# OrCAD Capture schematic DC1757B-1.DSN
size Custom; title: HIGH EFFICIENCY 12V / 12A BUCK-BOOST CONVERTER; rev: 1; company: TM
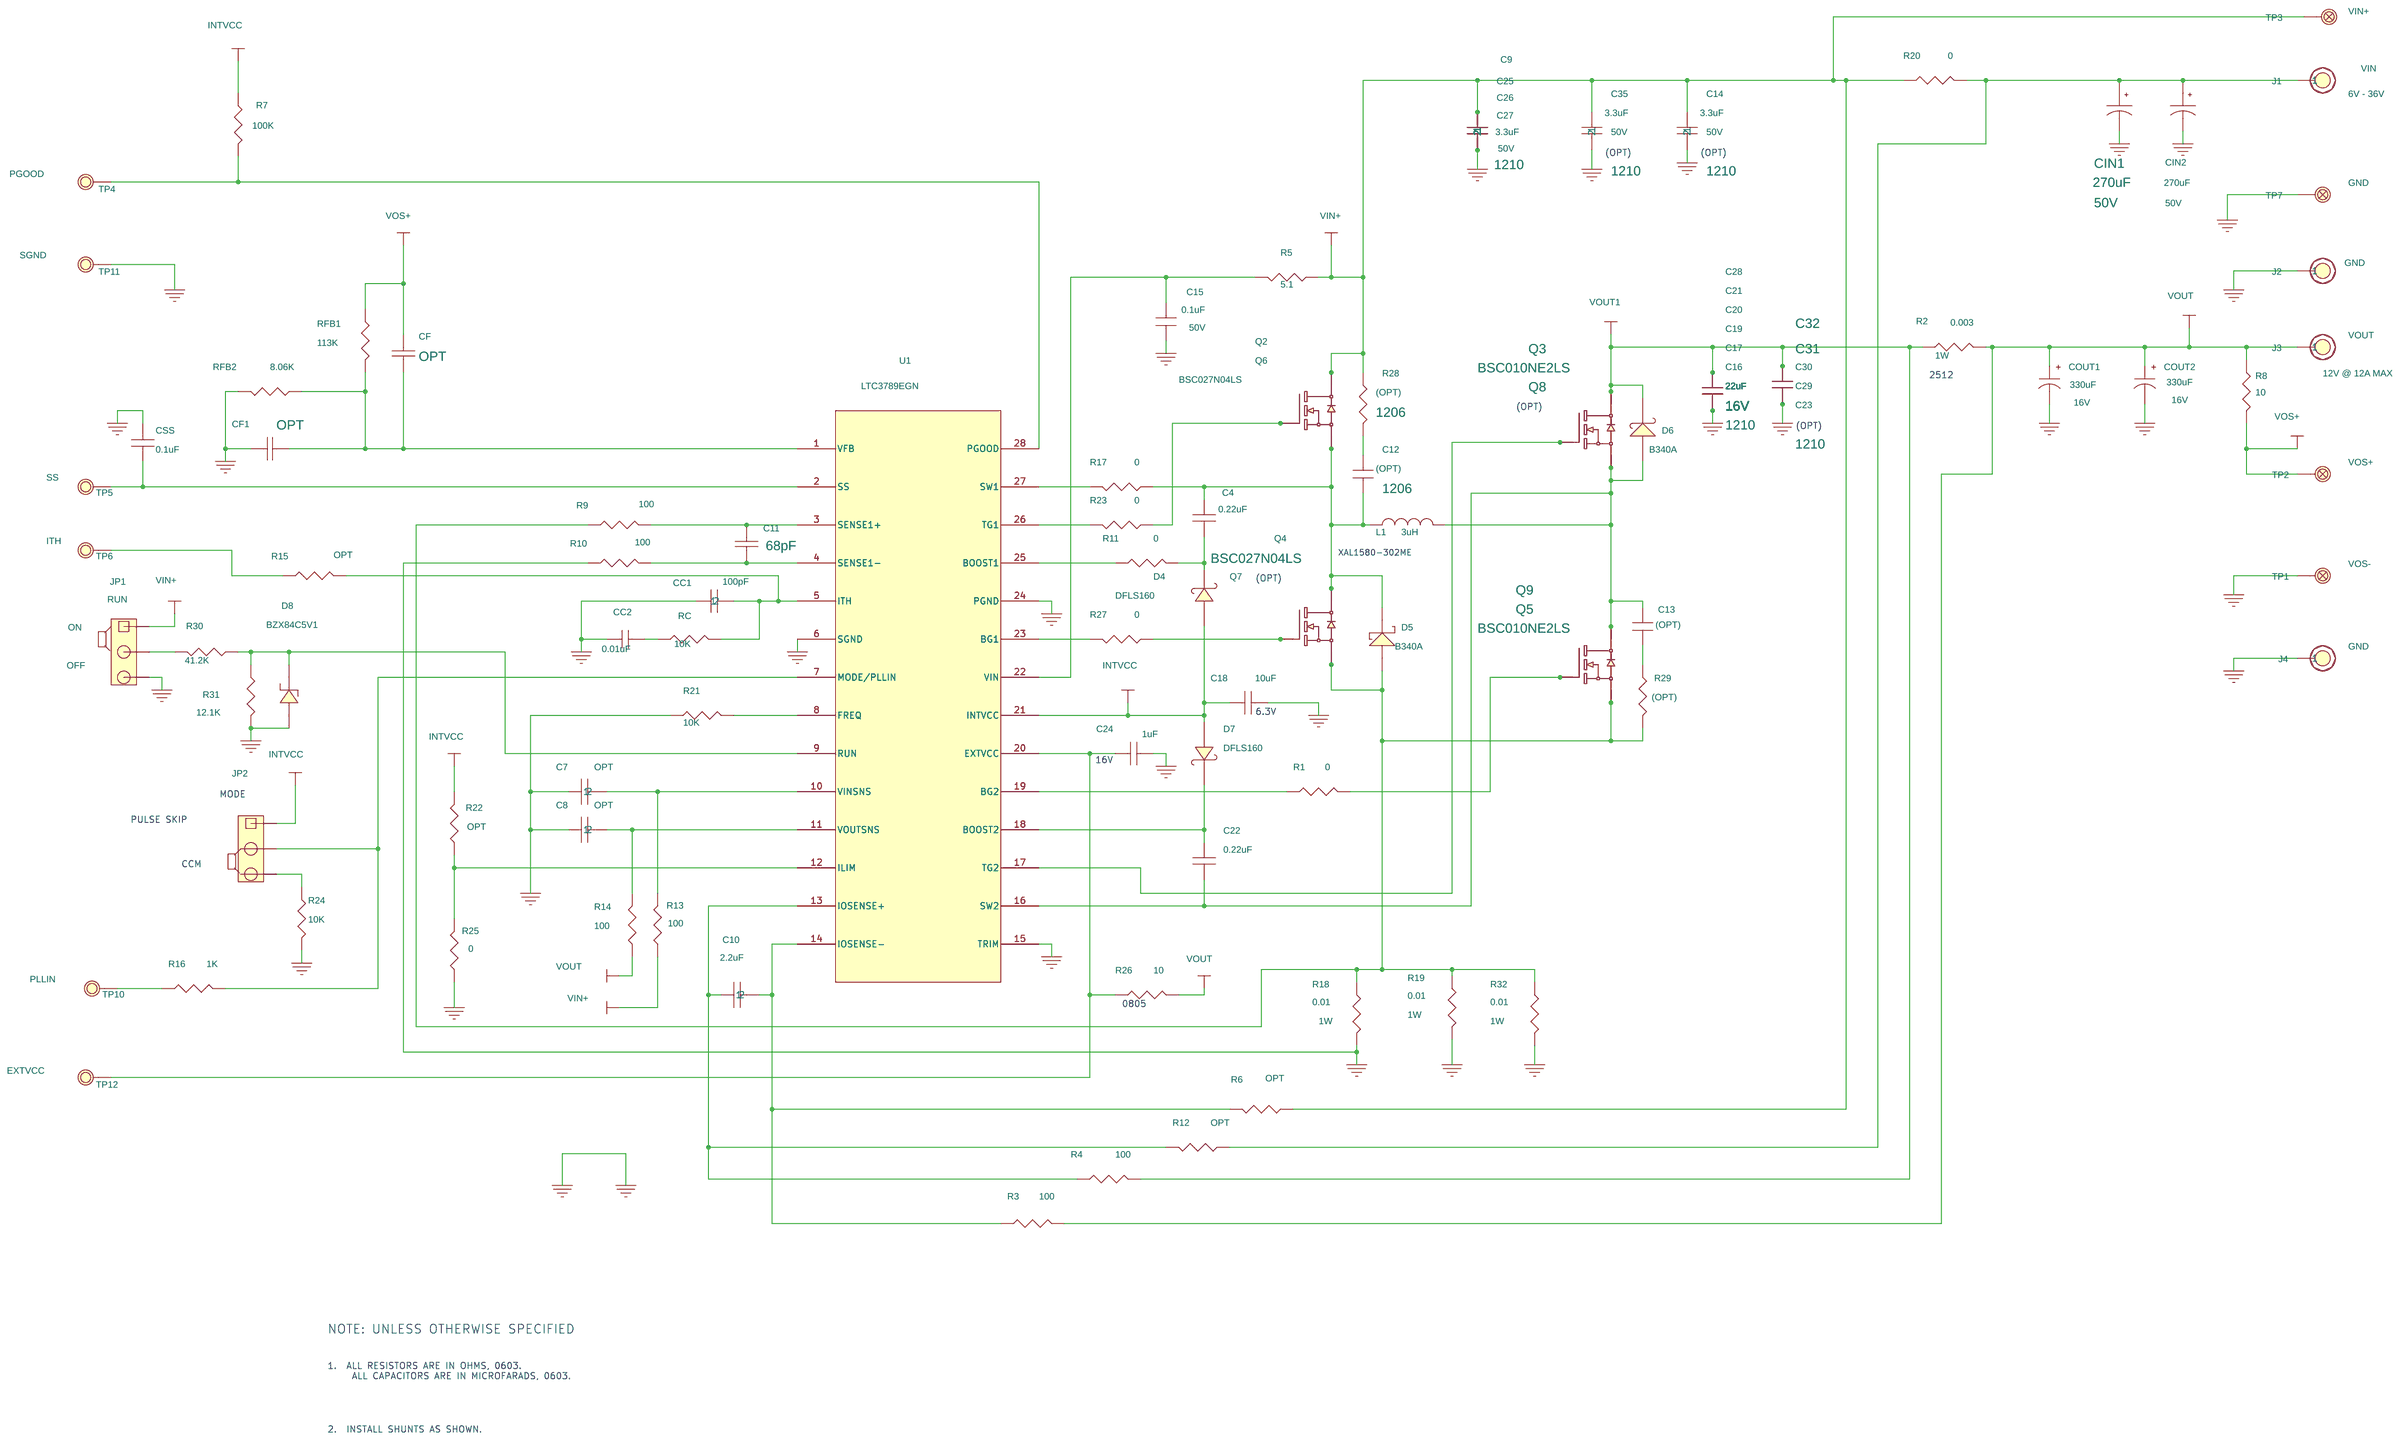
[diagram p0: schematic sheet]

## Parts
C4  0.22uF  [0603]
C7  OPT  [0603]
C8  OPT  [0603]
C9  3.3uF  [1210]
C10  2.2uF  [0603]
C11  68pF  [0603]
C12  (OPT)  [1206]
C13  (OPT)  [1206]
C14  3.3uF  [1210]
C15  0.1uF  [0603]
C16  22uF  [1210]
C17  22uF  [1210]
C18  10uF  [1206]
C19  22uF  [1210]
C20  22uF  [1210]
C21  22uF  [1210]
C22  0.22uF  [0603]
C23  OPT  [1210]
C24  1uF  [0603]
C25  3.3uF  [1210]
C26  3.3uF  [1210]
C27  3.3uF  [1210]
C28  22uF  [1210]
C29  OPT  [1210]
C30  OPT  [1210]
C31  OPT  [1210]
C32  OPT  [1210]
C35  3.3uF  [1210]
CC1  100pF  [0603]
CC2  0.01uF  [0603]
CF  OPT  [0603]
CF1  OPT  [0603]
CIN1  270uF  [CAP-ME-WX/10X20]
CIN2  270uF  [CAP-ME-WX/10X20]
COUT1  330uF  [CAP-ME-WX/10X20]
COUT2  330uF  [CAP-ME-WX/10X20]
CSS  0.1uF  [0603]
D4  DFLS160  [POWERDI123]
D5  B240A  [SMA]
D6  B240A  [SMA]
D7  DFLS160  [POWERDI123]
D8  BZX84C5V1  [SOT23]
J1  Banana Jack  [KEYSTONE-575-4]
J2  Banana Jack  [KEYSTONE-575-4]
J3  Banana Jack  [KEYSTONE-575-4]
J4  Banana Jack  [KEYSTONE-575-4]
JP1  3 Pins 2mm Ctrs.  [commcon2802s03g2]
JP2  3 Pins 2mm Ctrs.  [commcon2802s03g2]
L1  3uH  [XAL1580]
Q2  SiR422DP  [PWR_SO8(GDS)]
Q3  SiR496DP  [PWR_SO8(GDS)]
Q4  SiR422DP  [PWR_SO8(GDS)]
Q5  SiR496DP  [PWR_SO8(GDS)]
Q6  SiR422DP  [PWR_SO8(GDS)]
Q7  BSC027N04LS  [PWR_SO8(GDS)]
Q8  BSC010NE2LS  [PWR_SO8(GDS)]
Q9  BSC010NE2LS  [PWR_SO8(GDS)]
R1  0  [0603]
R2  0.003  [RL3720T-R018-F]
R3  100  [0603]
R4  100  [0603]
R5  5.1  [0805]
R6  OPT  [0603]
R7  100K  [0603]
R8  10  [0603]
R9  100  [0603]
R10  100  [0603]
R11  0  [0603]
R12  OPT  [0603]
R13  100  [0603]
R14  100  [0603]
R15  OPT  [0603]
R16  1K  [0603]
R17  0  [0603]
R18  0.01  [2512SENSE]
R19  0.01  [2512SENSE]
R20  0  [RN5326]
R21  10K  [0603]
R22  OPT  [0603]
R23  0  [0603]
R24  10K  [0603]
R25  0  [0603]
R26  10  [0805]
R27  0  [0603]
R28  (OPT)  [1206]
R29  (OPT)  [1206]
R30  41.2K  [0603]
R31  12.1K  [0603]
R32  0.01  [2512SENSE]
RC  10K  [0603]
RFB1  113K  [0603]
RFB2  8.06K  [0603]
TP1  Testpoint  [mill-max-2308]
TP2  Testpoint  [mill-max-2308]
TP3  Testpoint  [mill-max-2308]
TP4  Turret  [MILLMAX-2501-2]
TP5  Turret  [MILLMAX-2501-2]
TP6  Turret  [MILLMAX-2501-2]
TP7  Testpoint  [mill-max-2308]
TP10  Turret  [MILLMAX-2501-2]
TP11  Turret  [MILLMAX-2501-2]
TP12  Turret  [MILLMAX-2501-2]
U1  Volt. Reg.  [SSOP-28GN]
XJP1  2mm Ctrs.
XJP2B  2mm Ctrs.

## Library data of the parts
C4 C22 = EMK107BJ224MA: 3rd Part Field: X7R; 4th Part Field: KEMET; 5th Part Field: C0603C224K4RAC
C7 = C_1
C8 = C_2
C9 = C3225X5R1C226M_4: 1st Part Field: 50V; 3rd Part Field: X7R; 4th Part Field: TDK; 5th Part Field: C3225X7R1H335M
C10 = C
C11 CF = CAP0603
C12 C13 = CAP1206
C14 = C3225X5R1C226M_3: 1st Part Field: 50V; 3rd Part Field: X7R; 4th Part Field: TDK; 5th Part Field: C3225X7R1H335M
C15 = CAP1210: 1ST PART FIELD: 50V
C16 = C3225X7R1H335M_5: 1st Part Field: 16V; 3rd Part Field: X5R; 5th Part Field: C3225X5R1C226M
C17 = C3225X7R1H335M: 1st Part Field: 16V; 3rd Part Field: X5R; 5th Part Field: C3225X5R1C226M
C18 = C1608X5R0J475MT: 1st Part Field: 10V; 4th Part Field: KEMET; 5th Part Field: C1206C106K4PAC
C19 = C3225X7R1H335M_3: 1st Part Field: 16V; 3rd Part Field: X5R; 5th Part Field: C3225X5R1C226M
C20 = C3225X7R1H335M_6: 1st Part Field: 16V; 3rd Part Field: X5R; 5th Part Field: C3225X5R1C226M
C21 = C3225X7R1H335M_10: 1st Part Field: 16V; 3rd Part Field: X5R; 5th Part Field: C3225X5R1C226M
C23 = C3225X7R1H335M_2: 1st Part Field: 16V; 3rd Part Field: X5R; 5th Part Field: C3225X5R1C226M
C24 = LMK107BJ105MA: 1st Part Field: 16V; 3rd Part Field: X7R; 5th Part Field: EMK107BJ105MA
C25 = C3225X7R1H335M_9: 1st Part Field: 50V; 3rd Part Field: X7R; 4th Part Field: TDK; 5th Part Field: C3225X7R1H335M
C26 = C3225X5R1C226M_2: 1st Part Field: 50V; 3rd Part Field: X7R; 4th Part Field: TDK; 5th Part Field: C3225X7R1H335M
C27 = C3225X5R1C226M_1: 1st Part Field: 50V; 3rd Part Field: X7R; 4th Part Field: TDK; 5th Part Field: C3225X7R1H335M
C28 = C3225X7R1H335M_8: 1st Part Field: 16V; 3rd Part Field: X5R; 5th Part Field: C3225X5R1C226M
C29 = C3225X7R1H335M_1: 1st Part Field: 16V; 3rd Part Field: X5R; 5th Part Field: C3225X5R1C226M
C30 = C3225X7R1H335M_11: 1st Part Field: 16V; 3rd Part Field: X5R; 5th Part Field: C3225X5R1C226M
C31 = C3225X7R1H335M_4: 1st Part Field: 16V; 3rd Part Field: X5R; 5th Part Field: C3225X5R1C226M
C32 = C3225X7R1H335M_7: 1st Part Field: 16V; 3rd Part Field: X5R; 5th Part Field: C3225X5R1C226M
C35 = C3225X5R1C226M: 1st Part Field: 50V; 3rd Part Field: X7R; 4th Part Field: TDK; 5th Part Field: C3225X7R1H335M
CC1 = 06035A470KAT1A: 5th Part Field: 06035A470KAT2A
CC2 = 06033C103KAT2A
CF1 = CAP0603: 6th Part Field: opt
CIN1 = 35SVPD22M: 1st Part Field: 50V; 2nd Part Field: OPT; 5th Part Field: 50ME270WX
CIN2 = 35SVPD22M_1: 1st Part Field: 50V; 2nd Part Field: opt; 5th Part Field: 50ME270WX
COUT1 = CAP-OS-CON-F13: 1ST PART FIELD: 16V
COUT2 = CAP-OS-CON-F13: 1ST PART FIELD: 16V; opt: OPT
CSS = 06033C223KAT1A: 5th Part Field: 06033C223KAT2A
D4 D7 = DFLS160_0
D5 = B320A_0: 5th Part Field: B340A
D6 = B340LA_2: 5th Part Field: B340A
D8 = BZX84C2V4-C51
J1 = Keystone-575-4_0: 10th Part Field: 6V - 36V; 9th Part Field: VIN
J2 J4 = Keystone-575-4_0: 9th Part Field: GND
J3 = Keystone-575-4_0: 10th Part Field: 12V @ 12A MAX; 9th Part Field: VOUT
JP1 JP2 = Commcon2802s03g2: 11th Part Field: OFF; 12th Part Field: RUN; 9th Part Field: ON
L1 = FDA1254-4R7M
Q2 = MOSFET_0: 5th Part Field: BSC027N04LS
Q3 Q6 Q8 = MOSFET_0
Q4 = MOSFET-1
Q5 Q9 = MOSFET_0: 5th Part Field: <5th Part Field>
Q7 = Si422DP_2
R1 R3 R4 R6 R11-R14 = R
R2 = RL3720WT-R018-G: 2nd Part Field: 1W; 5th Part Field: RL3720WT-R004-G
R5 R17 R23 R27 = CR10-100JM
R7 = CR16-1002FM_2
R8 = CR16-100JM
R9 R10 R15 R16 = CR16-1241FM
R18 R19 R32 = RL3720WT-R018-G: 2nd Part Field: 1W; 5th Part Field: RL3720WT-R010-G
R20 = RL3720WT-R018-G: 5th Part Field: RL3720WT-R010-G
R21 = CR16-1002FM_3
R22 = CR16-1002FM_4
R24 R30 R31 RFB2 = CR16-8061FM
R25 = CR16-1002FM_1
R26 = CR16-1002FM
R28 R29 = AAC-1206
RC = CR16-1003FM
RFB1 = CR16-1133FM
TP1 = mill-max-2308-2: 9th Part Field: VOS-
TP2 = mill-max-2308-2: 9th Part Field: VOS+
TP3 = mill-max-2308-2: 9th Part Field: VIN+
TP4 = MillMax-2501-2_0: 9th Part Field: PGOOD
TP5 = MillMax-2501-2_0: 9th Part Field: SS
TP6 = MillMax-2501-2_0: 9th Part Field: ITH
TP7 = mill-max-2308-2: 9th Part Field: GND
TP10 = MillMax-2501-2_0: 9th Part Field: PLLIN
TP11 = MillMax-2501-2_0: 9th Part Field: SGND
TP12 = MillMax-2501-2_0: 9th Part Field: EXTVCC
U1 = LTC3780EG_4: 5th Part Field: LTC3789EGN
XJP1 XJP2B = CommconCCIJ2MM-138G

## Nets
GND: C7.1 C8.1 C9.2 C14.2 C15.2 C16.2 C17.2 C18.2 C19.2 C20.2 C21.2 C23.2 C24.2 C25.2 C26.2 C27.2 C28.2 C29.2 C30.2 C31.2 C32.2 C35.2 CC1.1 CC2.1 CF1.2 CIN1.2 CIN2.2 COUT1.2 COUT2.2 CSS.2 D8.1(ANODE) J2.1 J4.1 JP1.3 R10.1 R18.2 R19.2 R21.1 R24.2 R25.1 R31.2 R32.2 RFB2.2 TP1.1 TP7.1 TP11.1 U1.6(SGND) U1.15(TRIM) U1.24(PGND)
VIN+: C9.1 C14.1 C25.1 C26.1 C27.1 C35.1 JP1.1 Q2.D Q6.D R5.1 R6.1 R13.1 R20.1 R28.1 TP3.1
INTVCC: C18.1 D4.2(ANODE) D7.2(ANODE) JP2.1 R7.1 R22.2 U1.21(INTVCC)
VOS+: CF.1 R8.2 RFB1.1 TP2.1
VOUT: COUT1.1 COUT2.1 J3.1 R2.2 R3.2 R8.1 R14.1 R26.2
VOUT1: C16.1 C17.1 C19.1 C20.1 C21.1 C23.1 C28.1 C29.1 C30.1 C31.1 C32.1 D6.1(K) Q3.D Q8.D R2.1 R4.2
N965368: R7.2 TP4.1 U1.28(PGOOD)
N967628: CSS.1 TP5.1 U1.2(SS)
N978587: C4.1 C12.2 D5.1(K) L1.2 Q2.S Q4.D Q6.S Q7.D R17.1
N982428: C13.1 C22.2 D6.2(A) L1.1 Q3.S Q5.D Q8.S Q9.D U1.16(SW2)
N1026360: C11.1 R9.2 U1.3(SENSE1+)
N1026362: C11.2 R10.2 U1.4(SENSE1-)
N1091954: R23.2 U1.26(TG1)
N1092427: C4.2 D4.1(CATHODE) R11.2
N1094239: Q3.G Q8.G U1.17(TG2)
N1094509: C22.1 D7.1(CATHODE) U1.18(BOOST2)
N1108765: CF.2 CF1.1 RFB1.2 RFB2.1 U1.1(VFB)
N1110820: CC2.2 RC.1
N1110851: CC1.2 R15.2 RC.2 U1.5(ITH)
N1113516: CIN1.1 CIN2.1 J1.1 R12.1 R20.2
N1114055: C10.1 R4.1 R12.2 U1.13(IOSENSE+)
N1115043: D8.3(CATHODE) R30.1 R31.1 U1.9(RUN)
N1118277: D5.2(A) Q4.S Q5.S Q7.S Q9.S R9.1 R18.1 R19.1 R29.2 R32.1
N1121938: C24.1 R26.1 TP12.1 U1.20(EXTVCC)
N1125628: R22.1 R25.2 U1.12(ILIM)
N16492586: C15.1 R5.2 U1.22(VIN)
N16498430: C7.2 R13.2 U1.10(VINSNS)
N16499798: C8.2 R14.2 U1.11(VOUTSNS)
N16512527: C12.1 R28.2
N16523738: JP1.2 R30.2
N16546442: C10.2 R3.1 R6.2 U1.14(IOSENSE-)
N16563770: R21.2 U1.8(FREQ)
N16563853: JP2.2 R16.2 U1.7(MODE/PLLIN)
N16565942: R11.1 U1.25(BOOST1)
N16566360: R1.1 U1.19(BG2)
N16566649: Q5.G Q9.G R1.2
N16581336: Q4.G Q7.G R27.1
N16731965: C13.2 R29.1
N17050450: Q2.G Q6.G R23.1
N17320961: JP2.3 R24.1
N17426735: R15.1 TP6.1
N17428703: R16.1 TP10.1
N17441828: R17.2 U1.27(SW1)
N17446218: R27.2 U1.23(BG1)

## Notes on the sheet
- (OPT)
- (OPT)
- 2512
- (OPT)
- (OPT)
- XAL1580-302ME
- (OPT)
- 6.3V
- 16V
- MODE
- PULSE SKIP
- CCM
- 0805
- NOTE: UNLESS OTHERWISE SPECIFIED
- 1.  ALL RESISTORS ARE IN OHMS, 0603.
       ALL CAPACITORS ARE IN MICROFARADS, 0603.
- 2.  INSTALL SHUNTS AS SHOWN.
